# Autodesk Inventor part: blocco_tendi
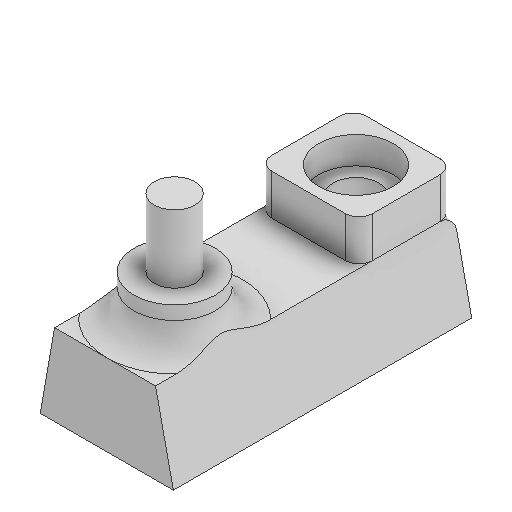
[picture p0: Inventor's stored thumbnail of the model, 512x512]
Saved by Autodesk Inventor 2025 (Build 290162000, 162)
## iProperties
Created: 2025-06
Part Number: blocco_tendi
Material: Generico
Document SubType Name: Modeling
Designer: Ryzen5700u
Density: 1 g/cm^3
Appearance: Default
Author: Ryzen5700u
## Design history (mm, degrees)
sketch "Schizzo1"
  geometry: L1 (-9.261, 2.15)-(-8.203, 8.15) reference; L2 (1.797, -2.23)-(-10.203, -2.23) reference; L3 (-0.203, 8.15)-(0.855, 2.15) reference; L4 (0.855, 2.15)-(-9.261, 2.15) reference; L5 (-8, 7)-(0, 7); L6 (-8.05, 8.15)-(-9.108, 2.15); L7 (-9.108, 2.15)-(0.703, 2.15); L8 (0.703, 2.15)-(-0.611, 8.15); L9 (-0.394, 7.158)-(2.74, 7.287); L10 (2.74, 7.287)-(2.972, -2.085); L11 (2.972, -2.085)-(-11.445, -2.276); L12 (-11.445, -2.276)-(-11.522, 7.3); L13 (-11.522, 7.3)-(-8.2, 7.3); L14 (-10.203, 8.15)-(-8.203, 8.15) reference; L15 (-0.203, 8.15)-(1.797, 8.15) reference; L16 (-8.203, 8.15)-(-0.203, 8.15); L17 (1.797, 8.15)-(1.797, -2.23) reference; L18 (-0.203, 8.15)-(1.797, 8.15) reference; L19 (-10.203, 8.15)-(-8.203, 8.15) reference; L20 (-10.203, -2.23)-(-10.203, 8.15) reference; 2 further points
  constraints: 20 end point, 4 point on line, 2 horizontal
  dimensions: "d0" = 0.15 distance between parallel lines of L1 L6
extrude "Estrusione1" new body sketch "Schizzo1" distance "d1" = 22; taper "d2" = 0 deg
sketch "Schizzo6"
  geometry: C1 r 1.5 at (3.848, 5) reference; 1 further point
extrude "Estrusione5" join sketch "Schizzo6" distance "d23" = 8; taper "d24" = 0 deg
sketch "Schizzo7"
  geometry: C1 r 1.5 at (3.848, 5) reference; C2 r 3 at (3.848, 5); 1 further point
  constraints: 1 centre point, 1 coincident
  dimensions: "d25" = 6 diameter of C2
extrude "Estrusione6" join sketch "Schizzo7" distance "d26" = 3; taper "d27" = 0 deg
fillet "Raccordo2" dims "d28" = 2
sketch "Schizzo8"
  geometry: L1 (0, -13.807)-(0, 0) reference; L2 (7.44, -13.522)-(7.44, 0) reference; L3 (0, 0)-(7.44, 0); L4 (7.44, 0)-(7.44, -7); L5 (7.44, -7)-(0, -7); L6 (0, -7)-(0, 0); 3 further points
  constraints: 8 end point, 2 parallel, 1 horizontal, 1 perpendicular, 1 point on line
  dimensions: "d29" = 7 distance of L3.end L4.end
extrude "Estrusione7" join sketch "Schizzo8" distance "d30" = 3; taper "d31" = 0 deg
sketch "Schizzo9"
  geometry: L1 (0, 0)-(0, -7) reference; L2 (0, -7)-(7.44, -7) reference; L3 (7.44, -7)-(7.44, 0) reference; L4 (7.44, 0)-(0, 0) reference; L5 (0, -13.807)-(0, -7) reference; L6 (0, -7)-(7.44, 0); L7 (0, 0)-(7.44, -7); 2 further points
  constraints: 4 end point, 1 midpoint
  node "Linea chiusa proiettata1"
sketch "Schizzo10"
  geometry: L1 (-0.703, 2.15)-(9.108, 2.15) reference; L2 (4.203, 2.15)-(4.203, 11.15); L3 (5.703, 11.15)-(2.703, 11.15) reference; L4 (1.453, 6.848)-(6.953, 6.848); L5 (6.953, 6.848)-(6.953, 4.448); L6 (6.953, 4.448)-(1.453, 4.448); L7 (1.453, 4.448)-(1.453, 6.848); L8 (1.453, 6.848)-(6.953, 4.448); L9 (6.953, 6.848)-(1.453, 4.448); 2 further points
  constraints: 14 end point, 3 midpoint, 2 parallel, 2 perpendicular, 2 point on line, 1 horizontal
  dimensions: "d39" = 5.5 distance of L5.end L6.end; "d40" = 2.4 distance of L4.end L5.end
extrude "Estrusione8" cut sketch "Schizzo10" stored distance "d41" = 3; taper "d42" = 0 deg
fillet "Raccordo3" dims "d43" = 1
hole "Foro3" sketch "Schizzo9" diameter "d44" = 3.4; stored, may be unused: countersink angle "d48" = 90 deg, drill point angle "d50" = 118 deg; dims "d45" = 6, "d46" = 5.5, "d47" = 2, "d49" = 8
node "Solido1"
node "Riferimento1"
node "Riferimento2"
node "Riferimento3"
node "Riferimento4"
